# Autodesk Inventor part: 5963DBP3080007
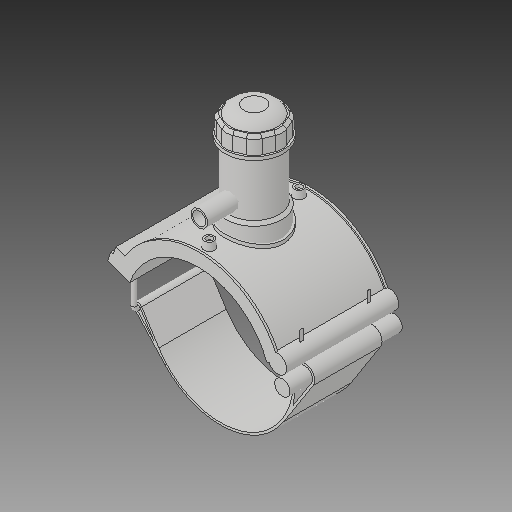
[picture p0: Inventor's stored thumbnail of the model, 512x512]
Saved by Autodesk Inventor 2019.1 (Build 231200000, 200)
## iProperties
Created: 2017-07
Part Number: 5963DBP3080007
Material: Generic
Description: PLASSON TAPPING SADDLE 8''DIPS x 3/4''IPS
Document SubType Name: Modeling
Designer: KIM
Density: 1 g/cm^3
Appearance: Default
Author: KIM
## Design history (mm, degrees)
derived "5963DBP_5963BUP.ipt"
feature "Solid1::5963DBP_5963BUP.ipt"
feature "Solid2::5963DBP_5963BUP.ipt"
feature "Solid3::5963DBP_5963BUP.ipt"
tag "TaggingFeature1"
body "Solid1"
body "Solid2"
body "Solid3"
other parameters: "d0" = 228.9, "d2" = 269.748, "d3" = 57.225, "d4" = 176.022, "d5" = 0, "d6" = 0.1, "d8" = 0, "d19" = 6, "d20" = 6, "d21" = 105.6132, "d23" = 0, "d24" = 52.8066, "d26" = 0, "d27" = 3, "d28" = 3, "d29" = 3, "d30" = 76.3, "d31" = 6, "d32" = 0, "d33" = 0, "d34" = 0.6, "d40" = 138.07248, "d41" = 91.56, "d43" = 0, "d45" = 0, "d47" = 238.3752, "d70" = 15, "d72" = 0, "d73" = 6, "d75" = 5, "d76" = 0, "d77" = 11.445, "d78" = 144.45, "d79" = 15, "d80" = 70.4088, "d82" = 5 deg, "d84" = 4, "d85" = 14, "d86" = 0, "d87" = 3, "d88" = 0, "d89" = 1, "d90" = 1, "d91" = 140.8176, "d92" = 0, "d93" = 0.5, "d94" = 120.47368, "d96" = 270.83448, "d97" = 3.52044, "d98" = 0, "d120" = 140 deg, "d121" = 24.228, "d122" = 20 deg, "d123" = 531.048, "d124" = 159.3144, "d126" = 0, "d143" = 235.767, "d145" = 28.17231, "d149" = 3.4335, "d150" = 30.98954, "d153" = 176.022, "d154" = 0, "d156" = 132.762, "d157" = 160 deg, "d159" = 7.3248, "d161" = 3.4335, "d162" = 105.6132, "d163" = 0, "d164" = 114.45, "d167" = 22.89, "d168" = 129.5239, "d170" = 3.4335, "d172" = 0, "d173" = 1, "d175" = 114.45, "d176" = 20 deg, "d177" = 16.023, "d178" = 36.624, "d180" = 0, "d183" = 14.6496, "d184" = 12.8184, "d185" = 57.20715, "d186" = 57.20715, "d187" = 132.762, "d188" = 10.9872, "d189" = 16.023, "d190" = 0, "d191" = 199.143, "d193" = 7.3248, "d194" = 6.16077, "d195" = 90 deg, "d197" = 0, "d199" = 0, "d200" = 18.312, "d202" = 0, "d203" = 177.038, "d204" = 86.982, "d205" = 64.092, "d206" = 77.826, "d207" = 132.7785, "d208" = 138.08964, "d209" = 164.64534, "d210" = 78.7416, "d211" = 91.56, "d212" = 73.248, "d213" = 46.5516, "d216" = 0, "d217" = 22.89, "d218" = 22.89, "d219" = 4.578, "d222" = 228.9, "d224" = 0, "d225" = 65.024, "d226" = 26.6, "d227" = 21.28, "d228" = 86.106, "d230" = 4.578, "d_" = 228.9, "B_" = 179.832, "L_" = 176.022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
